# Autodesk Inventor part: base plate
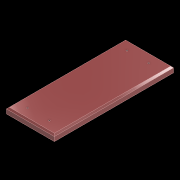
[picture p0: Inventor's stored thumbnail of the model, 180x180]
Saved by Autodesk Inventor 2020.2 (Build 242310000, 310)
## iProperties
Manager: PART
Company: 5
Category: 15
Created: 2020-10
Part Number: base plate
Material: Generic
Document SubType Name: Modeling
Designer: Apardo
Density: 1 g/cm^3
Appearance: Chestnut
Vendor: 15
Project: PLATE ROLLING MACHINE
Cost Center: 1
Description: BASE PLATE
Engineer: STEEL C45
Stock Number: 1.1
Engr Approved By: D. JAEGER
Author: Apardo
Revision Number: 1.0
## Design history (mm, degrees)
sketch "Sketch1"
  geometry: L1 (82.5, 205)-(-82.5, 205); L2 (-82.5, 205)-(-82.5, -205); L3 (-82.5, -205)-(82.5, -205); L4 (82.5, -205)-(82.5, 205); L5 (82.5, 205)-(-82.5, -205); L6 (-82.5, 205)-(82.5, -205); 1 further point
  constraints: 12 end point, 2 midpoint, 2 parallel, 1 horizontal, 1 perpendicular
  dimensions: "d0" = 165 distance of L3.end L2.end; "d1" = 410 distance of L3.end L1.start
extrude "Extrusion1" new body sketch "Sketch1" stored distance "d2" = 20; taper "d3" = 0 deg
chamfer "Chamfer1" distance "d4" = 5; stored, may be unused: second distance "d5" = 2, angle "d6" = 45 deg
sketch "Sketch2"
  geometry: 5 further points
  constraints: 2 horizontal alignment, 2 vertical alignment
  dimensions: "d7" = 342 distance of point (31, -171) point (31, 171); "d8" = 75 distance of point (31, 171) point (-44, 171); "d9" = 171 vertical distance of point (0, 0) point (31, 171) (= 0.5 x d7); "d18" = 44 horizontal distance of point (0, 0) point (-44, 171)
hole "Hole1" sketch "Sketch2" at (31, 171), (-44, 171), (31, -171), (-44, -171) diameter "d11" = 4.917; stored, may be unused: countersink angle "d15" = 90 deg, drill point angle "d17" = 118 deg; dims "d12" = 20, "d13" = 4, "d14" = 2, "d16" = 17.1
body "Solid1"
